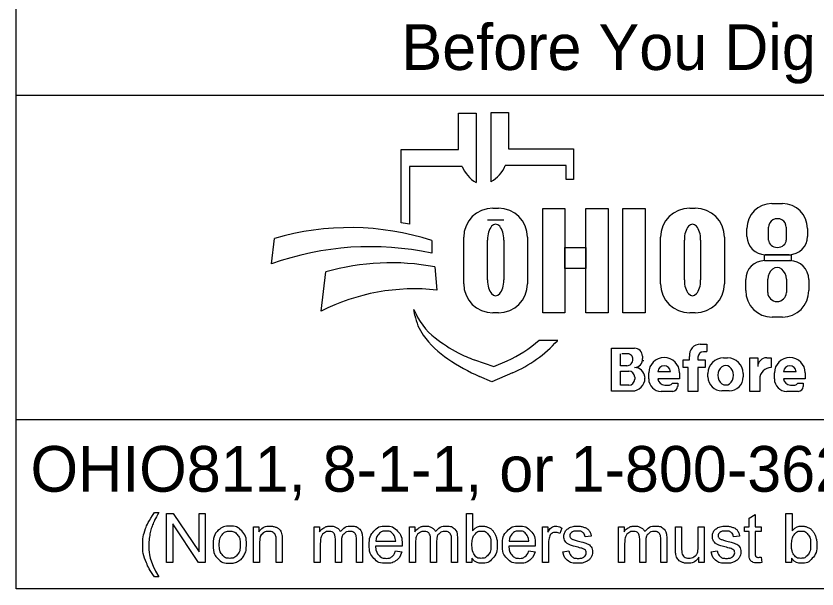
# Model space of a CAD drawing. Extents: x 0 to 34, y 0 to 22.
# Drawn here: x 2.378 to 4.831, y 2.143 to 3.897 of the extents above; entities that cross this region are included whole.
import ezdxf

# ---------------------------------------------------------------- set-up
doc = ezdxf.new("R2010")
doc.units = 0
doc.layers.add('SH_Data', color=7, linetype='Continuous')
doc.layers.add('SH_Text', color=7, linetype='Continuous')

msp = doc.modelspace()

# ---------------------------------------------------------------- linework, layer by layer
at = {"layer": 'SH_Data'}
for p, q in [((2.3775, 2.1428), (2.3775, 4.4803)), ((2.3775, 3.6553), (6.6275, 3.6553)), ((6.6275, 2.6607), (2.3775, 2.6607)), ((6.6275, 2.1428), (2.3775, 2.1428))]:
    msp.add_line(p, q, dxfattribs=at)
at = {"layer": 'SH_Text'}
for p, q in [((3.7335, 3.4883), (3.7335, 3.5998)), ((3.7335, 3.5998), (3.7872, 3.5998)), ((3.7872, 3.5998), (3.7872, 3.3877)), ((3.8329, 3.39), (3.8329, 3.6021)), ((3.8329, 3.6021), (3.8865, 3.6021)), ((3.8865, 3.6021), (3.8865, 3.4906)), ((3.5576, 3.2644), (3.5576, 3.4883)), ((3.5576, 3.4883), (3.7335, 3.4883)), ((3.8865, 3.4906), (4.0857, 3.4906)), ((4.0857, 3.4906), (4.0857, 3.3968)), ((3.5828, 3.4369), (3.5828, 3.26)), ((3.7439, 3.4369), (3.5828, 3.4369)), ((4.0625, 3.4392), (3.8761, 3.4392)), ((4.0625, 3.3968), (4.0625, 3.4392)), ((4.0857, 3.3968), (4.0625, 3.3968)), ((4.6931, 3.3231), (4.7258, 3.3231)), ((3.8385, 3.3091), (3.8551, 3.3091)), ((4.4416, 3.3091), (4.4581, 3.3091)), ((3.8718, 3.2721), (3.822, 3.2721)), ((4.6168, 3.2225), (4.6168, 3.2468)), ((4.683, 3.2111), (4.683, 3.2504)), ((4.7371, 3.2504), (4.7371, 3.2111)), ((4.8022, 3.2468), (4.8022, 3.2225)), ((3.1602, 3.1381), (3.1696, 3.2162)), ((3.7491, 3.0776), (3.7491, 3.2196)), ((3.9445, 3.2196), (3.9445, 3.0776)), ((4.3521, 3.0776), (4.3521, 3.2196)), ((4.5476, 3.2196), (4.5476, 3.0776)), ((3.6509, 3.2097), (3.6509, 3.1709)), ((3.822, 3.089), (3.822, 3.2114)), ((3.8718, 3.2114), (3.8718, 3.089)), ((4.425, 3.089), (4.425, 3.2114)), ((4.4748, 3.2114), (4.4748, 3.089)), ((4.7462, 3.1665), (4.6728, 3.1665)), ((4.671, 3.1482), (4.7483, 3.1482)), ((3.6608, 3.1291), (3.6671, 3.0582)), ((3.312, 2.9936), (3.3267, 3.1137)), ((4.6131, 3.0563), (4.6131, 3.0903)), ((4.6806, 3.0503), (4.6806, 3.0912)), ((4.7374, 3.0912), (4.7374, 3.0503)), ((4.8062, 3.0903), (4.8062, 3.0563)), ((3.5997, 2.9807), (3.5967, 2.9986)), ((3.8551, 2.9882), (3.8385, 2.9882)), ((4.4581, 2.9882), (4.4416, 2.9882)), ((4.7252, 2.9753), (4.6941, 2.9753)), ((3.98, 2.9048), (4.0375, 2.9048)), ((4.2013, 2.749), (4.2013, 2.8798)), ((4.2013, 2.8798), (4.2725, 2.8798)), ((4.4739, 2.8926), (4.4934, 2.8926)), ((4.4934, 2.8926), (4.4934, 2.8696)), ((4.2293, 2.8263), (4.2293, 2.8632)), ((4.2545, 2.8632), (4.2332, 2.8632)), ((4.2963, 2.856), (4.2963, 2.8481)), ((4.4406, 2.8442), (4.4406, 2.8546)), ((4.4667, 2.8526), (4.4667, 2.8442)), ((4.4934, 2.8691), (4.4832, 2.8691)), ((4.5451, 2.8508), (4.5573, 2.8508)), ((4.6254, 2.7478), (4.6254, 2.8505)), ((4.6254, 2.8505), (4.6499, 2.8505)), ((4.6499, 2.8505), (4.6499, 2.8237)), ((4.6772, 2.8505), (4.691, 2.8505)), ((4.691, 2.8505), (4.691, 2.8209)), ((3.7816, 2.8444), (3.841, 2.8239)), ((3.841, 2.8239), (3.8821, 2.8417)), ((4.2487, 2.8263), (4.2293, 2.8263)), ((4.4213, 2.8212), (4.4213, 2.8442)), ((4.4213, 2.8442), (4.4406, 2.8442)), ((4.4667, 2.8442), (4.4883, 2.8442)), ((4.4883, 2.8442), (4.4883, 2.8212)), ((3.8983, 2.8044), (3.835, 2.7769)), ((4.2293, 2.7669), (4.2293, 2.8097)), ((4.2293, 2.8097), (4.2548, 2.8097)), ((4.3159, 2.7858), (4.3159, 2.8042)), ((4.3824, 2.8082), (4.3439, 2.8082)), ((4.4104, 2.8042), (4.4104, 2.7866)), ((4.4362, 2.8212), (4.4213, 2.8212)), ((4.4362, 2.7478), (4.4362, 2.8212)), ((4.4883, 2.8212), (4.4667, 2.8212)), ((4.4667, 2.8212), (4.4667, 2.7478)), ((4.4973, 2.7922), (4.4973, 2.8029)), ((4.6051, 2.8029), (4.6051, 2.7922)), ((4.7008, 2.7858), (4.7008, 2.8042)), ((4.7674, 2.8082), (4.7288, 2.8082)), ((4.7953, 2.8042), (4.7953, 2.7866)), ((3.835, 2.7769), (3.7976, 2.7934)), ((4.2729, 2.7916), (4.2729, 2.7853)), ((4.3043, 2.7887), (4.3043, 2.7884)), ((4.4104, 2.7866), (4.344, 2.7866)), ((4.3876, 2.7729), (4.4045, 2.7729)), ((4.4045, 2.7729), (4.4045, 2.7631)), ((4.6559, 2.786), (4.6559, 2.7478)), ((4.7953, 2.7866), (4.7289, 2.7866)), ((4.7725, 2.7729), (4.7894, 2.7729)), ((4.7894, 2.7729), (4.7894, 2.7631)), ((4.265, 2.749), (4.2013, 2.749)), ((4.2546, 2.7669), (4.2293, 2.7669)), ((4.3649, 2.7673), (4.379, 2.7673)), ((4.5623, 2.7494), (4.5401, 2.7494)), ((4.7498, 2.7673), (4.7639, 2.7673)), ((4.3892, 2.7478), (4.3538, 2.7478)), ((4.4667, 2.7478), (4.4362, 2.7478)), ((4.6559, 2.7478), (4.6254, 2.7478)), ((4.7742, 2.7478), (4.7388, 2.7478))]:
    msp.add_line(p, q, dxfattribs=at)
for points in [[(3.991, 3.3081), (4.0589, 3.3081), (4.0589, 2.9881), (3.991, 2.9881)], [(4.1231, 3.3081), (4.1911, 3.3081), (4.1911, 2.9881), (4.1231, 2.9881)], [(4.2364, 3.3081), (4.3052, 3.3081), (4.3052, 2.9881), (4.2364, 2.9881)], [(4.0589, 3.1882), (4.1231, 3.1882), (4.1231, 3.1242), (4.0589, 3.1242)], [(4.6706, 3.1665), (4.7523, 3.1665), (4.7523, 3.1481), (4.6706, 3.1481)]]:
    msp.add_lwpolyline(points, close=True, dxfattribs=at)
for points in [[(2.8021, 2.3766), (2.8153, 2.3766)], [(2.8389, 2.2239), (2.8389, 2.3741), (2.8592, 2.3741), (2.9382, 2.2561), (2.9382, 2.3741), (2.9572, 2.3741), (2.9572, 2.2239), (2.9369, 2.2239), (2.8579, 2.3419), (2.8579, 2.2239), (2.8389, 2.2239)], [(3.7743, 2.2239), (3.7573, 2.2239), (3.7573, 2.3741), (3.7757, 2.3741), (3.7757, 2.3206)], [(4.6233, 2.2558), (4.6233, 2.3185), (4.6097, 2.3185), (4.6097, 2.3328), (4.6233, 2.3328), (4.6233, 2.3597), (4.6417, 2.3708), (4.6417, 2.3328), (4.6601, 2.3328), (4.6601, 2.3185), (4.6417, 2.3185), (4.6417, 2.2547)], [(4.7534, 2.2239), (4.7363, 2.2239), (4.7363, 2.3741), (4.7548, 2.3741), (4.7548, 2.3206)], [(3.1048, 2.2239), (3.1048, 2.3328), (3.1214, 2.3328), (3.1214, 2.3173)], [(3.2912, 2.2239), (3.2912, 2.3328), (3.3077, 2.3328), (3.3077, 2.3174)], [(3.5826, 2.2239), (3.5826, 2.3328), (3.5991, 2.3328), (3.5991, 2.3174)], [(3.9904, 2.2239), (3.9904, 2.3328), (4.007, 2.3328), (4.007, 2.3163)], [(4.2236, 2.2239), (4.2236, 2.3328), (4.2401, 2.3328), (4.2401, 2.3174)], [(4.3979, 2.2654), (4.3979, 2.3328), (4.4164, 2.3328), (4.4164, 2.2724)], [(4.4676, 2.2745), (4.4676, 2.3328), (4.4861, 2.3328), (4.4861, 2.2239), (4.4696, 2.2239)], [(4.0495, 2.3293), (4.043, 2.3122)], [(3.1233, 2.2833), (3.1233, 2.2239), (3.1048, 2.2239)], [(3.1932, 2.2908), (3.1932, 2.2239), (3.1748, 2.2239), (3.1748, 2.2901)], [(3.3743, 2.2871), (3.3743, 2.2239), (3.3559, 2.2239), (3.3559, 2.2946)], [(3.4388, 2.2986), (3.4388, 2.2239), (3.4203, 2.2239), (3.4203, 2.2924)], [(3.4799, 2.2887), (3.5406, 2.2887)], [(3.6657, 2.2871), (3.6657, 2.2239), (3.6473, 2.2239), (3.6473, 2.2946)], [(3.7301, 2.2986), (3.7301, 2.2239), (3.7117, 2.2239), (3.7117, 2.2924)], [(3.8879, 2.2887), (3.9486, 2.2887)], [(4.1394, 2.3046), (4.1213, 2.3022)], [(4.3067, 2.2871), (4.3067, 2.2239), (4.2883, 2.2239), (4.2883, 2.2946)], [(4.3711, 2.2986), (4.3711, 2.2239), (4.3527, 2.2239), (4.3527, 2.2924)], [(4.594, 2.3046), (4.5759, 2.3022)], [(3.3097, 2.2803), (3.3097, 2.2239), (3.2912, 2.2239)], [(3.56, 2.2736), (3.4788, 2.2736)], [(3.5404, 2.2591), (3.5595, 2.2567)], [(3.601, 2.2803), (3.601, 2.2239), (3.5826, 2.2239)], [(3.968, 2.2736), (3.8868, 2.2736)], [(3.9484, 2.2591), (3.9675, 2.2567)], [(4.0088, 2.2809), (4.0088, 2.2239), (3.9904, 2.2239)], [(4.053, 2.2564), (4.0712, 2.2593)], [(4.242, 2.2803), (4.242, 2.2239), (4.2236, 2.2239)], [(4.5076, 2.2564), (4.5258, 2.2593)], [(3.7743, 2.2375), (3.7743, 2.2239)], [(4.4696, 2.2239), (4.4696, 2.24)], [(4.6601, 2.2404), (4.6628, 2.2241)], [(4.7534, 2.2375), (4.7534, 2.2239)], [(2.8153, 2.1798), (2.8021, 2.1798)]]:
    msp.add_lwpolyline(points, dxfattribs=at)
for centre, radius, start, end in [((3.8353, 3.4736), 0.0985, 201.9296, 240.7469), ((3.7847, 3.476), 0.0985, 299.2531, 338.0704), ((4.6931, 3.2468), 0.0763, 90, 180), ((4.7258, 3.2468), 0.0763, 0, 90), ((3.8385, 3.2196), 0.0895, 90, 180), ((3.8551, 3.2196), 0.0895, 0, 90), ((4.4416, 3.2196), 0.0895, 90, 180), ((4.4581, 3.2196), 0.0895, 0, 90), ((3.4295, 2.4554), 0.8191, 79.2074, 81.0007), ((3.3997, 2.4302), 0.8191, 72.1402, 106.3144), ((4.6728, 3.2225), 0.056, 180, 270), ((4.7462, 3.2225), 0.056, 270, 0), ((3.4628, 2.2991), 0.8919, 77.8238, 109.8274), ((3.5267, 2.4094), 0.7322, 79.44, 105.8467), ((4.671, 3.0903), 0.0579, 90, 180), ((4.7483, 3.0903), 0.0579, 0, 90), ((3.8385, 3.0776), 0.0895, 180, 270), ((3.8551, 3.0776), 0.0895, 270, 0), ((4.4416, 3.0776), 0.0895, 180, 270), ((4.4581, 3.0776), 0.0895, 270, 0), ((3.5987, 2.4262), 0.6357, 83.8248, 116.8021), ((4.6941, 3.0563), 0.081, 180, 270), ((4.7252, 3.0563), 0.081, 270, 0), ((3.7841, 3.0707), 0.2008, 201.0457, 232.5314), ((3.741, 3.0048), 0.1433, 189.6817, 216.0884), ((3.8747, 3.1022), 0.3088, 216.0884, 235.7167), ((3.9766, 3.3219), 0.5173, 232.5314, 241.794), ((3.7387, 3.1722), 0.3602, 293.4582, 312.0712), ((3.7387, 3.1722), 0.401, 293.4582, 317.8286), ((4.2725, 2.856), 0.0238, 0, 90), ((4.4739, 2.859), 0.0335, 90, 187.5187), ((4.0412, 3.3465), 0.6044, 235.7167, 246.2325), ((3.8914, 3.1631), 0.3371, 241.794, 250.9821), ((4.2505, 2.8463), 0.0169, 357.8325, 90), ((4.2721, 2.8453), 0.0243, 270, 6.6529), ((4.3631, 2.8042), 0.0473, 0, 180), ((4.4832, 2.8526), 0.0165, 90, 180), ((4.5451, 2.8029), 0.0478, 90, 180), ((4.5573, 2.8029), 0.0478, 0, 90), ((4.6768, 2.8237), 0.0269, 89.2449, 180), ((4.7481, 2.8042), 0.0473, 0, 180), ((4.2487, 2.845), 0.0187, 270, 2.0582), ((4.2827, 2.8438), 0.0175, 347.4023, 0), ((4.3632, 2.8072), 0.0193, 2.9632, 177.0368), ((4.7481, 2.8072), 0.0193, 2.9632, 177.0368), ((4.2548, 2.7916), 0.0181, 0, 90), ((4.2722, 2.7889), 0.0321, 4.0748, 90), ((4.6908, 2.786), 0.0349, 89.6033, 180), ((4.2546, 2.7853), 0.0184, 270, 0), ((4.265, 2.7884), 0.0393, 270, 0), ((4.2714, 2.7887), 0.033, 0, 11.7502), ((4.3538, 2.7858), 0.038, 180, 270), ((4.3649, 2.7883), 0.021, 184.827, 270), ((4.379, 2.7767), 0.00938, 270, 335.9979), ((4.5401, 2.7922), 0.0428, 180, 270), ((4.5623, 2.7922), 0.0428, 270, 0), ((4.7388, 2.7858), 0.038, 180, 270), ((4.7498, 2.7883), 0.021, 184.827, 270), ((4.7639, 2.7767), 0.00938, 270, 335.9979), ((4.3892, 2.7631), 0.0152, 270, 0), ((4.7742, 2.7631), 0.0152, 270, 0)]:
    msp.add_arc(centre, radius, start, end, dxfattribs=at)
for centre, major_axis, ratio, start_param, end_param in [((4.71, 3.2504), (0.0271, 0), 0.969373, 0, 3.141593), ((3.8469, 3.2114), (0, 0.0484), 0.514403, 4.712389, 7.853982), ((4.4499, 3.2114), (0, 0.0484), 0.514403, 4.712389, 7.853982), ((4.71, 3.2111), (0.0271, 0), 0.818453, 3.141593, 6.283185), ((4.709, 3.0912), (0, 0.0358), 0.794529, 4.712389, 7.853982), ((3.8469, 3.089), (0, 0.0484), 0.514403, 1.570796, 4.712389), ((4.4499, 3.089), (0, 0.0484), 0.514403, 1.570796, 4.712389), ((4.709, 3.0503), (0.0284, 0), 0.959837, 3.141593, 6.283185), ((4.5517, 2.7976), (0, 0.029), 0.832186, 4.712389, 7.853982), ((4.5517, 2.7976), (0, 0.0302), 0.797287, 1.570796, 4.712389)]:
    msp.add_ellipse(centre, major_axis=major_axis, ratio=ratio, start_param=start_param, end_param=end_param, dxfattribs=at)
for points in [[(2.8021, 2.1798), (2.7869, 2.199), (2.7763, 2.2248), (2.7657, 2.2506), (2.7657, 2.2783), (2.7657, 2.3026), (2.7736, 2.325), (2.7829, 2.3509), (2.8021, 2.3766)], [(2.8153, 2.3766), (2.8029, 2.3553), (2.7989, 2.3462), (2.7927, 2.332), (2.7891, 2.3167), (2.7847, 2.2975), (2.7847, 2.2782), (2.7847, 2.2289), (2.8153, 2.1798)], [(2.9814, 2.2783), (2.9814, 2.3085), (2.9981, 2.3231), (3.0122, 2.3352), (3.0323, 2.3352), (3.0547, 2.3352), (3.069, 2.3205), (3.0832, 2.3058), (3.0832, 2.2799), (3.0832, 2.2589), (3.0769, 2.2469), (3.0706, 2.2348), (3.0586, 2.2282), (3.0466, 2.2215), (3.0323, 2.2215), (3.0095, 2.2215), (2.9954, 2.2362), (2.9814, 2.2508), (2.9814, 2.2783)], [(3.1214, 2.3173), (3.1334, 2.3352), (3.156, 2.3352), (3.1659, 2.3352), (3.1741, 2.3316), (3.1823, 2.3281), (3.1864, 2.3224), (3.1905, 2.3166), (3.1922, 2.3087), (3.1932, 2.3036), (3.1932, 2.2908)], [(3.3077, 2.3174), (3.3128, 2.3254), (3.3214, 2.3303), (3.3299, 2.3352), (3.3407, 2.3352), (3.3528, 2.3352), (3.3606, 2.3301), (3.3683, 2.3251), (3.3715, 2.3161), (3.3844, 2.3352), (3.4051, 2.3352), (3.4213, 2.3352), (3.43, 2.3262), (3.4388, 2.3172), (3.4388, 2.2986)], [(3.5595, 2.2567), (3.555, 2.24), (3.5428, 2.2307), (3.5306, 2.2215), (3.5117, 2.2215), (3.4878, 2.2215), (3.4738, 2.2362), (3.4598, 2.2509), (3.4598, 2.2774), (3.4598, 2.3049), (3.474, 2.32), (3.4881, 2.3352), (3.5106, 2.3352), (3.5324, 2.3352), (3.5463, 2.3203), (3.5601, 2.3055), (3.5601, 2.2785), (3.5601, 2.2769), (3.56, 2.2736)], [(3.5991, 2.3174), (3.6042, 2.3254), (3.6127, 2.3303), (3.6212, 2.3352), (3.6321, 2.3352), (3.6442, 2.3352), (3.6519, 2.3301), (3.6597, 2.3251), (3.6628, 2.3161), (3.6758, 2.3352), (3.6965, 2.3352), (3.7127, 2.3352), (3.7214, 2.3262), (3.7301, 2.3172), (3.7301, 2.2986)], [(3.7757, 2.3206), (3.7874, 2.3352), (3.8055, 2.3352), (3.8155, 2.3352), (3.8245, 2.3311), (3.8335, 2.3271), (3.8392, 2.3198), (3.845, 2.3124), (3.8483, 2.3021), (3.8516, 2.2918), (3.8516, 2.28), (3.8516, 2.252), (3.8378, 2.2368), (3.8239, 2.2215), (3.8046, 2.2215), (3.7853, 2.2215), (3.7743, 2.2375)], [(3.9675, 2.2567), (3.963, 2.24), (3.9508, 2.2307), (3.9386, 2.2215), (3.9196, 2.2215), (3.8958, 2.2215), (3.8818, 2.2362), (3.8678, 2.2509), (3.8678, 2.2774), (3.8678, 2.3049), (3.882, 2.32), (3.8961, 2.3352), (3.9186, 2.3352), (3.9404, 2.3352), (3.9543, 2.3203), (3.9681, 2.3055), (3.9681, 2.2785), (3.9681, 2.2769), (3.968, 2.2736)], [(4.007, 2.3163), (4.0133, 2.3278), (4.0187, 2.3315), (4.0241, 2.3352), (4.0305, 2.3352), (4.0398, 2.3352), (4.0495, 2.3293)], [(4.0712, 2.2593), (4.0727, 2.2483), (4.0798, 2.2425), (4.0868, 2.2366), (4.0995, 2.2366), (4.1122, 2.2366), (4.1184, 2.2418), (4.1245, 2.247), (4.1245, 2.254), (4.1245, 2.2602), (4.1191, 2.2638), (4.1153, 2.2663), (4.1002, 2.2701), (4.0799, 2.2752), (4.072, 2.2789), (4.0642, 2.2827), (4.0601, 2.2893), (4.0561, 2.2959), (4.0561, 2.3038), (4.0561, 2.3111), (4.0594, 2.3173), (4.0628, 2.3235), (4.0685, 2.3276), (4.0728, 2.3308), (4.0803, 2.333), (4.0877, 2.3352), (4.0962, 2.3352), (4.109, 2.3352), (4.1187, 2.3315), (4.1284, 2.3278), (4.133, 2.3215), (4.1377, 2.3152), (4.1394, 2.3046)], [(4.2401, 2.3174), (4.2452, 2.3254), (4.2537, 2.3303), (4.2622, 2.3352), (4.2731, 2.3352), (4.2852, 2.3352), (4.2929, 2.3301), (4.3007, 2.3251), (4.3038, 2.3161), (4.3168, 2.3352), (4.3375, 2.3352), (4.3537, 2.3352), (4.3624, 2.3262), (4.3711, 2.3172), (4.3711, 2.2986)], [(4.5258, 2.2593), (4.5273, 2.2483), (4.5343, 2.2425), (4.5414, 2.2366), (4.554, 2.2366), (4.5668, 2.2366), (4.5729, 2.2418), (4.5791, 2.247), (4.5791, 2.254), (4.5791, 2.2602), (4.5736, 2.2638), (4.5698, 2.2663), (4.5548, 2.2701), (4.5345, 2.2752), (4.5266, 2.2789), (4.5188, 2.2827), (4.5147, 2.2893), (4.5107, 2.2959), (4.5107, 2.3038), (4.5107, 2.3111), (4.514, 2.3173), (4.5173, 2.3235), (4.5231, 2.3276), (4.5274, 2.3308), (4.5348, 2.333), (4.5423, 2.3352), (4.5508, 2.3352), (4.5636, 2.3352), (4.5733, 2.3315), (4.583, 2.3278), (4.5876, 2.3215), (4.5922, 2.3152), (4.594, 2.3046)], [(4.7548, 2.3206), (4.7664, 2.3352), (4.7846, 2.3352), (4.7946, 2.3352), (4.8036, 2.3311), (4.8125, 2.3271), (4.8183, 2.3198), (4.8241, 2.3124), (4.8274, 2.3021), (4.8306, 2.2918), (4.8306, 2.28), (4.8306, 2.252), (4.8168, 2.2368), (4.803, 2.2215), (4.7836, 2.2215), (4.7644, 2.2215), (4.7534, 2.2375)], [(3.0003, 2.2783), (3.0003, 2.2574), (3.0094, 2.247), (3.0185, 2.2366), (3.0323, 2.2366), (3.046, 2.2366), (3.0551, 2.2471), (3.0642, 2.2575), (3.0642, 2.279), (3.0642, 2.2991), (3.0551, 2.3095), (3.0459, 2.3199), (3.0323, 2.3199), (3.0185, 2.3199), (3.0094, 2.3096), (3.0003, 2.2992), (3.0003, 2.2783)], [(3.1748, 2.2901), (3.1748, 2.3013), (3.1726, 2.3069), (3.1705, 2.3125), (3.165, 2.3158), (3.1595, 2.3191), (3.1521, 2.3191), (3.1404, 2.3191), (3.1318, 2.3117), (3.1233, 2.3042), (3.1233, 2.2833)], [(3.3559, 2.2946), (3.3559, 2.3069), (3.3514, 2.313), (3.3469, 2.3191), (3.3366, 2.3191), (3.3288, 2.3191), (3.3222, 2.315), (3.3156, 2.311), (3.3126, 2.3031), (3.3097, 2.2952), (3.3097, 2.2803)], [(3.4203, 2.2924), (3.4203, 2.3035), (3.4185, 2.3083), (3.4168, 2.3132), (3.412, 2.3162), (3.4073, 2.3191), (3.401, 2.3191), (3.3895, 2.3191), (3.3819, 2.3115), (3.3743, 2.3039), (3.3743, 2.2871)], [(3.5406, 2.2887), (3.5394, 2.3025), (3.5337, 2.3094), (3.5249, 2.3201), (3.5108, 2.3201), (3.4981, 2.3201), (3.4894, 2.3115), (3.4808, 2.303), (3.4799, 2.2887)], [(3.6473, 2.2946), (3.6473, 2.3069), (3.6428, 2.313), (3.6383, 2.3191), (3.628, 2.3191), (3.6202, 2.3191), (3.6136, 2.315), (3.607, 2.311), (3.604, 2.3031), (3.601, 2.2952), (3.601, 2.2803)], [(3.7117, 2.2924), (3.7117, 2.3035), (3.7099, 2.3083), (3.7081, 2.3132), (3.7034, 2.3162), (3.6987, 2.3191), (3.6923, 2.3191), (3.6809, 2.3191), (3.6733, 2.3115), (3.6657, 2.3039), (3.6657, 2.2871)], [(3.7741, 2.2792), (3.7741, 2.2596), (3.7794, 2.2509), (3.7881, 2.2366), (3.8029, 2.2366), (3.815, 2.2366), (3.8238, 2.2471), (3.8326, 2.2576), (3.8326, 2.2784), (3.8326, 2.2998), (3.8241, 2.3099), (3.8157, 2.3201), (3.8038, 2.3201), (3.7917, 2.3201), (3.7829, 2.3096), (3.7741, 2.299), (3.7741, 2.2792)], [(3.9486, 2.2887), (3.9474, 2.3025), (3.9417, 2.3094), (3.9328, 2.3201), (3.9188, 2.3201), (3.9061, 2.3201), (3.8974, 2.3115), (3.8888, 2.303), (3.8879, 2.2887)], [(4.043, 2.3122), (4.0363, 2.3162), (4.0295, 2.3162), (4.0235, 2.3162), (4.0187, 2.3125), (4.0139, 2.3089), (4.0119, 2.3024), (4.0088, 2.2926), (4.0088, 2.2809)], [(4.1213, 2.3022), (4.1201, 2.3106), (4.1142, 2.3153), (4.1083, 2.3201), (4.0975, 2.3201), (4.0848, 2.3201), (4.0794, 2.3159), (4.0739, 2.3116), (4.0739, 2.306), (4.0739, 2.3024), (4.0762, 2.2995), (4.0785, 2.2966), (4.0833, 2.2946), (4.086, 2.2936), (4.0996, 2.2899), (4.1192, 2.2847), (4.1269, 2.2813), (4.1347, 2.278), (4.1391, 2.2717), (4.1435, 2.2653), (4.1435, 2.2559), (4.1435, 2.2467), (4.1381, 2.2386), (4.1327, 2.2304), (4.1226, 2.226), (4.1124, 2.2215), (4.0996, 2.2215), (4.0784, 2.2215), (4.0672, 2.2303), (4.0561, 2.2391), (4.053, 2.2564)], [(4.2883, 2.2946), (4.2883, 2.3069), (4.2838, 2.313), (4.2793, 2.3191), (4.269, 2.3191), (4.2612, 2.3191), (4.2546, 2.315), (4.248, 2.311), (4.245, 2.3031), (4.242, 2.2952), (4.242, 2.2803)], [(4.3527, 2.2924), (4.3527, 2.3035), (4.3509, 2.3083), (4.3491, 2.3132), (4.3444, 2.3162), (4.3397, 2.3191), (4.3333, 2.3191), (4.3219, 2.3191), (4.3143, 2.3115), (4.3067, 2.3039), (4.3067, 2.2871)], [(4.5759, 2.3022), (4.5747, 2.3106), (4.5688, 2.3153), (4.5629, 2.3201), (4.5521, 2.3201), (4.5394, 2.3201), (4.5339, 2.3159), (4.5285, 2.3116), (4.5285, 2.306), (4.5285, 2.3024), (4.5308, 2.2995), (4.533, 2.2966), (4.5378, 2.2946), (4.5406, 2.2936), (4.5542, 2.2899), (4.5737, 2.2847), (4.5815, 2.2813), (4.5893, 2.278), (4.5937, 2.2717), (4.5981, 2.2653), (4.5981, 2.2559), (4.5981, 2.2467), (4.5927, 2.2386), (4.5873, 2.2304), (4.5772, 2.226), (4.567, 2.2215), (4.5542, 2.2215), (4.5329, 2.2215), (4.5218, 2.2303), (4.5107, 2.2391), (4.5076, 2.2564)], [(4.7532, 2.2792), (4.7532, 2.2596), (4.7585, 2.2509), (4.7672, 2.2366), (4.782, 2.2366), (4.7941, 2.2366), (4.8029, 2.2471), (4.8116, 2.2576), (4.8116, 2.2784), (4.8116, 2.2998), (4.8032, 2.3099), (4.7948, 2.3201), (4.7828, 2.3201), (4.7708, 2.3201), (4.762, 2.3096), (4.7532, 2.299), (4.7532, 2.2792)], [(3.4788, 2.2736), (3.4799, 2.2557), (3.489, 2.2462), (3.4981, 2.2366), (3.5117, 2.2366), (3.5219, 2.2366), (3.5291, 2.242), (3.5362, 2.2473), (3.5404, 2.2591)], [(3.8868, 2.2736), (3.8879, 2.2557), (3.897, 2.2462), (3.9061, 2.2366), (3.9197, 2.2366), (3.9299, 2.2366), (3.937, 2.242), (3.9442, 2.2473), (3.9484, 2.2591)], [(4.4696, 2.24), (4.4569, 2.2215), (4.4351, 2.2215), (4.4255, 2.2215), (4.4171, 2.2252), (4.4088, 2.2289), (4.4047, 2.2345), (4.4007, 2.2401), (4.3991, 2.2482), (4.3979, 2.2536), (4.3979, 2.2654)], [(4.4164, 2.2724), (4.4164, 2.258), (4.4175, 2.253), (4.4192, 2.2457), (4.4249, 2.2416), (4.4305, 2.2374), (4.4388, 2.2374), (4.4471, 2.2374), (4.4543, 2.2417), (4.4616, 2.2459), (4.4646, 2.2533), (4.4676, 2.2606), (4.4676, 2.2745)], [(4.6628, 2.2241), (4.655, 2.2224), (4.6488, 2.2224), (4.6388, 2.2224), (4.6333, 2.2256), (4.6278, 2.2288), (4.6255, 2.234), (4.6233, 2.2392), (4.6233, 2.2558)], [(4.6417, 2.2547), (4.6417, 2.2468), (4.6427, 2.2445), (4.6436, 2.2423), (4.6458, 2.2409), (4.648, 2.2396), (4.6521, 2.2396), (4.6551, 2.2396), (4.6601, 2.2404)]]:
    msp.add_open_spline(points, degree=3, dxfattribs=at)

# ---------------------------------------------------------------- texts
for s, p in [('Before You Dig', (3.5583, 3.7321)), ('OHIO811, 8-1-1, or 1-800-362-2764', (2.422, 2.4406))]:
    msp.add_text(s, height=0.14, dxfattribs=at).set_placement(p)

doc.saveas('drawing.dxf')
